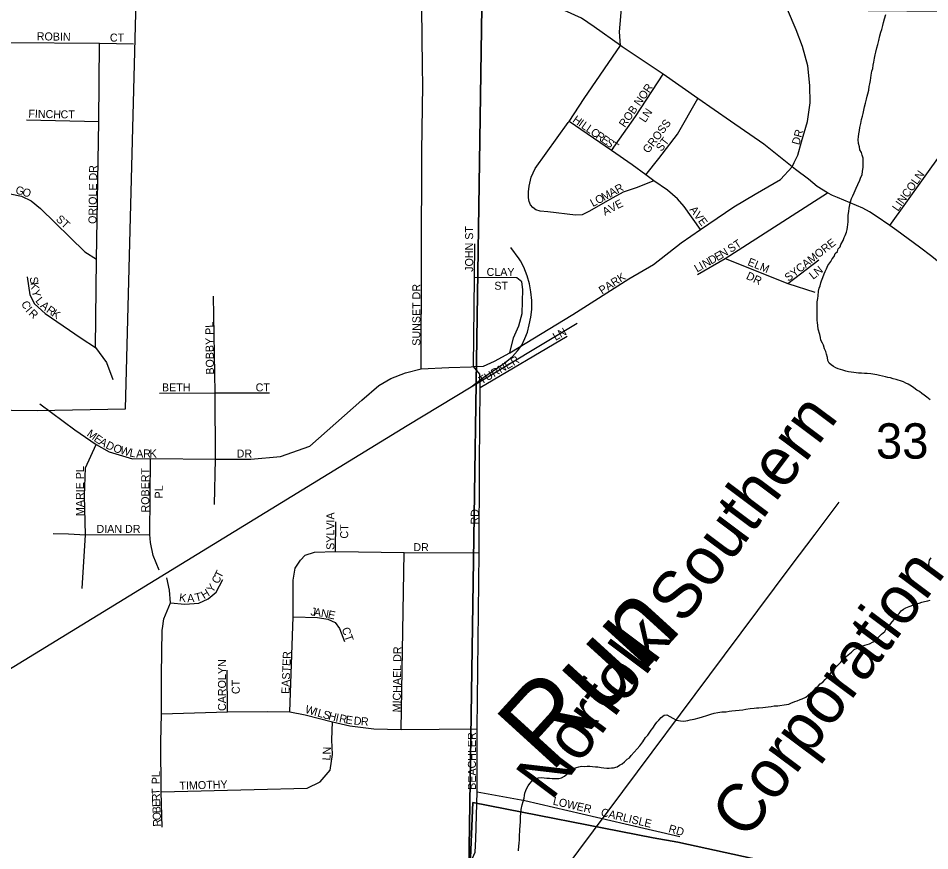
# Model space of a CAD drawing. Extents: x 0 to 1064, y 0 to 440.
# Drawn here: x 135.19 to 152.46, y 390.63 to 406.41 of the extents above; entities that cross this region are included whole.
import ezdxf

# ---------------------------------------------------------------- set-up
doc = ezdxf.new("R2010")
doc.units = 0
for name, color, linetype in [('GM_X_City_Street', 7, 'Continuous'), ('GM_X_City_Street_Text', 7, 'Continuous'), ('GM_X_Corporation', 7, 'Continuous'), ('GM_X_Minor_River', 7, 'Continuous'), ('GM_X_Minor_River_Text', 7, 'Continuous'), ('GM_X_Rail_Line', 7, 'Continuous'), ('GM_X_Rail_Line_Text', 7, 'Continuous'), ('GM_X_Section', 7, 'Continuous'), ('GM_X_Section_Text', 7, 'Continuous'), ('GM_X_State_Route', 7, 'Continuous'), ('GM_X_Township_Subdivision', 7, 'Continuous'), ('GM_X_Township_Subdivision_Text', 7, 'Continuous')]:
    doc.layers.add(name, color=color, linetype=linetype)

msp = doc.modelspace()

# ---------------------------------------------------------------- linework, layer by layer
at = {"layer": 'GM_X_City_Street'}
for points in [[(146.598, 405.89), (146.58, 406.153), (146.624, 406.662), (146.636, 406.826), (146.64, 406.976), (146.673, 407.878), (146.698, 409.622), (146.564, 411.865)], [(142.822, 399.767), (142.839, 403.891), (142.853, 405.135), (142.85, 405.488), (142.839, 406.606)], [(149.888, 403.672), (149.957, 403.815), (150.029, 404.063), (150.14, 404.45), (150.191, 404.805), (150.185, 405.131), (150.148, 405.504), (150.048, 405.87), (149.924, 406.19), (149.763, 406.571)], [(145.611, 404.43), (145.625, 404.448), (145.911, 404.885), (146.598, 405.89)], [(151.702, 402.478), (152.669, 403.837), (152.814, 404.028), (152.905, 404.103), (153.059, 404.203), (153.314, 404.359), (155.028, 405.406), (155.405, 405.642), (155.646, 405.776), (155.732, 405.812), (155.843, 405.827), (156.113, 405.807), (156.319, 405.816)], [(146.429, 403.9), (146.88, 404.548), (147.406, 405.346)], [(147.078, 403.441), (147.325, 403.752), (147.676, 404.21), (148.061, 404.889)], [(147.231, 403.329), (146.897, 403.195), (146.648, 403.114), (146.454, 403.008), (146.001, 402.746), (145.871, 402.68), (145.746, 402.674), (145.223, 402.737), (145.078, 402.752), (144.998, 402.779), (144.937, 402.82), (144.896, 402.872), (144.869, 402.938), (144.854, 403.006), (144.854, 403.121), (144.868, 403.227), (144.907, 403.396), (144.98, 403.562), (145.611, 404.43)], [(148.111, 402.408), (147.807, 402.841), (147.681, 402.984), (147.487, 403.151), (147.231, 403.329), (147.078, 403.441), (146.819, 403.629), (146.429, 403.9), (145.625, 404.448)], [(143.773, 399.806), (143.816, 399.807), (144.005, 399.814), (144.213, 399.91), (144.503, 400.067), (145.695, 400.794), (146.757, 401.473), (147.222, 401.741), (147.746, 402.153), (148.111, 402.408), (148.744, 402.833), (149.147, 403.073), (149.631, 403.35), (149.85, 403.592), (149.888, 403.672)], [(148.055, 401.55), (148.579, 401.854), (150.519, 403.098)], [(143.816, 399.807), (143.837, 401.497), (143.841, 402.133)], [(148.579, 401.854), (149.768, 401.382), (150.276, 401.217)], [(149.768, 401.382), (150.353, 401.83)], [(144.503, 400.067), (144.571, 400.354), (144.672, 400.578), (144.735, 400.812), (144.749, 401.27), (144.732, 401.413), (144.637, 401.49), (143.837, 401.497)], [(138.911, 397.198), (138.932, 398.051), (138.925, 399.309), (138.892, 401.14)], [(143.944, 399.412), (145.591, 400.386)], [(135.605, 399.099), (136.269, 398.61), (136.668, 398.331), (136.919, 398.191), (137.36, 398.058), (137.702, 398.065), (138.932, 398.051), (139.596, 398.051), (140.163, 398.107), (140.713, 398.297), (141.703, 399.17), (142.022, 399.452), (142.252, 399.582), (142.528, 399.69), (142.822, 399.767)], [(142.822, 399.767), (143.351, 399.788), (143.773, 399.806)], [(143.883, 391.754), (143.885, 392.948), (143.925, 396.279), (143.932, 397.971), (143.944, 399.412), (143.938, 399.666), (143.816, 399.807)], [(137.87, 399.302), (138.925, 399.309), (139.953, 399.309)], [(136.408, 395.602), (136.465, 396.618), (136.451, 397.359), (136.469, 397.891), (136.668, 398.331)], [(137.865, 395.95), (137.75, 396.227), (137.696, 396.474), (137.688, 396.625), (137.702, 398.065)], [(141.201, 396.305), (141.207, 396.864)], [(135.857, 396.646), (136.144, 396.639), (136.465, 396.618), (137.688, 396.625)], [(140.339, 393.264), (140.398, 395.068), (140.403, 395.761), (140.439, 395.989), (140.537, 396.141), (140.627, 396.233), (140.806, 396.292), (141.201, 396.305), (142.5, 396.284), (143.925, 396.279)], [(142.444, 392.935), (142.5, 396.284)], [(137.924, 394.847), (137.954, 395.029), (138.079, 395.333), (138.061, 395.575), (138.007, 395.805)], [(138.079, 395.333), (138.347, 395.307), (138.615, 395.325), (138.791, 395.407), (138.941, 395.532), (139.066, 395.774)], [(140.398, 395.068), (140.862, 395.052), (141.056, 395.022), (141.194, 394.958), (141.28, 394.843), (141.372, 394.598)], [(137.918, 391.085), (137.898, 391.751), (137.893, 392.695), (137.908, 393.226), (137.908, 393.966), (137.918, 394.813), (137.924, 394.847)], [(139.16, 393.267), (139.153, 394.057)], [(137.908, 393.226), (139.16, 393.267), (139.908, 393.272), (140.339, 393.264), (140.627, 393.213), (141.148, 393.075), (141.472, 393.004), (141.926, 392.948), (142.444, 392.935), (143.885, 392.948)], [(137.898, 391.751), (139.661, 391.797), (140.666, 391.818), (140.911, 391.94), (141.099, 392.162), (141.143, 392.458), (141.13, 392.736), (141.148, 393.075)], [(132.75, 390.394), (134.757, 390.374), (136.62, 390.376), (136.91, 390.371), (137.013, 390.348), (137.089, 390.3), (137.137, 390.226), (137.163, 389.662), (137.204, 389.562), (137.277, 389.485), (137.431, 389.468), (143.546, 390.366), (143.775, 390.453), (143.847, 390.611), (143.862, 390.856), (143.883, 391.754)], [(143.883, 391.754), (144.786, 391.59), (146.689, 391.147), (147.725, 390.902)]]:
    msp.add_lwpolyline(points, dxfattribs=at)
at = {"layer": 'GM_X_Corporation'}
for points in [[(134.575, 398.988), (135.551, 398.978), (137.228, 399.009), (137.428, 406.746)], [(155.515, 389.139), (151.907, 389.876), (147.686, 390.8), (147.217, 390.877), (143.803, 391.547), (143.754, 390.348), (143.764, 389.078), (140.31, 384.326), (140.059, 384.509), (139.72, 384.042), (139.97, 383.86), (137.379, 383.845), (137.356, 382.071), (137.389, 379.897), (136.812, 379.062), (134.041, 375.398)], [(136.812, 379.062), (137.389, 379.897), (137.356, 382.071), (137.379, 383.845), (139.97, 383.86), (141.136, 383.87), (143.777, 387.503), (143.764, 389.078), (143.754, 390.348), (143.803, 391.547), (147.217, 390.877), (147.686, 390.8), (151.907, 389.876), (155.515, 389.139)]]:
    msp.add_lwpolyline(points, dxfattribs=at)
at = {"layer": 'GM_X_Minor_River'}
for points in [[(151.192, 404.603), (151.205, 404.664), (151.219, 404.731), (151.239, 404.797), (151.258, 404.876), (151.272, 404.93), (151.285, 404.978), (151.299, 405.045), (151.306, 405.112), (151.319, 405.166), (151.333, 405.227), (151.34, 405.281), (151.347, 405.33), (151.361, 405.402), (151.374, 405.457), (151.382, 405.517), (151.395, 405.578), (151.409, 405.651), (151.422, 405.711), (151.436, 405.765), (151.456, 405.844), (151.469, 405.911), (151.489, 405.983), (151.509, 406.074), (151.529, 406.146), (151.548, 406.195), (151.568, 406.273), (151.581, 406.328), (151.601, 406.394), (151.621, 406.479)], [(151.66, 399.601), (151.618, 399.614), (151.563, 399.628), (151.503, 399.641), (151.455, 399.654), (151.412, 399.655), (151.34, 399.669), (151.267, 399.677), (151.218, 399.678), (151.164, 399.685), (151.103, 399.686), (151.019, 399.694), (150.916, 399.709), (150.867, 399.722), (150.807, 399.741), (150.765, 399.754), (150.723, 399.768), (150.675, 399.787), (150.633, 399.812), (150.591, 399.843), (150.549, 399.875), (150.526, 399.924), (150.521, 399.979), (150.498, 400.04), (150.487, 400.095), (150.464, 400.144), (150.441, 400.211), (150.424, 400.254), (150.395, 400.31), (150.384, 400.359), (150.373, 400.414), (150.345, 400.518), (150.334, 400.585), (150.329, 400.64), (150.324, 400.682), (150.325, 400.737), (150.326, 400.786), (150.321, 400.834), (150.322, 400.877), (150.323, 400.919), (150.324, 400.968), (150.325, 401.035), (150.333, 401.096), (150.34, 401.15), (150.348, 401.235), (150.361, 401.296), (150.381, 401.338), (150.394, 401.392), (150.407, 401.434), (150.432, 401.495), (150.458, 401.567), (150.477, 401.609), (150.497, 401.657), (150.528, 401.724), (150.579, 401.796), (150.604, 401.85), (150.647, 401.891), (150.667, 401.952), (150.71, 401.987), (150.723, 402.036), (150.761, 402.077), (150.774, 402.12), (150.818, 402.198), (150.837, 402.252), (150.856, 402.294), (150.876, 402.355), (150.889, 402.403), (150.896, 402.451), (150.911, 402.548), (150.912, 402.615), (150.913, 402.676), (150.921, 402.743), (150.928, 402.809), (150.942, 402.87), (150.955, 402.93), (150.975, 402.991), (151, 403.045), (151.026, 403.099), (151.064, 403.19), (151.096, 403.256), (151.128, 403.34), (151.147, 403.394), (151.173, 403.443), (151.18, 403.509), (151.194, 403.582), (151.196, 403.685), (151.192, 403.758), (151.175, 403.813), (151.164, 403.862), (151.134, 403.912), (151.124, 403.973), (151.107, 404.034), (151.102, 404.107), (151.103, 404.162), (151.111, 404.216), (151.124, 404.283), (151.131, 404.337), (151.151, 404.416), (151.165, 404.489), (151.179, 404.549), (151.192, 404.603)], [(152.464, 399.176), (152.398, 399.226), (152.35, 399.264), (152.303, 399.301), (152.261, 399.333), (152.213, 399.364), (152.153, 399.408), (152.111, 399.439), (152.045, 399.477), (152.003, 399.496), (151.955, 399.522), (151.901, 399.535), (151.859, 399.548), (151.817, 399.561), (151.762, 399.575), (151.714, 399.594), (151.66, 399.601)], [(152.467, 395.965), (152.45, 396.014), (152.439, 396.057), (152.446, 396.1), (152.453, 396.142), (152.484, 396.184)], [(151.959, 395.21), (152.002, 395.24), (152.063, 395.262), (152.106, 395.274), (152.18, 395.309), (152.253, 395.325), (152.302, 395.342), (152.357, 395.36), (152.418, 395.37), (152.46, 395.382)], [(146.426, 392.204), (146.468, 392.204), (146.535, 392.226), (146.579, 392.256), (146.628, 392.279), (146.677, 392.321), (146.727, 392.368), (146.77, 392.398), (146.801, 392.44), (146.857, 392.505), (146.913, 392.565), (146.963, 392.625), (147.019, 392.696), (147.075, 392.78), (147.119, 392.828), (147.182, 392.918), (147.213, 392.96), (147.257, 393.026), (147.288, 393.068), (147.325, 393.109), (147.369, 393.157), (147.424, 393.205), (147.479, 393.209), (147.533, 393.178), (147.587, 393.146), (147.659, 393.108), (147.732, 393.094), (147.786, 393.093), (147.835, 393.098), (147.877, 393.103), (147.92, 393.115), (147.993, 393.125), (148.091, 393.153), (148.152, 393.17), (148.231, 393.199), (148.311, 393.222), (148.372, 393.239), (148.439, 393.255), (148.518, 393.266), (148.597, 393.27), (148.658, 393.281), (148.707, 393.286), (148.774, 393.291), (148.847, 393.301), (148.914, 393.306), (148.974, 393.317), (149.054, 393.327), (149.133, 393.338), (149.175, 393.343), (149.218, 393.342), (149.291, 393.352), (149.394, 393.362), (149.449, 393.367), (149.51, 393.378), (149.577, 393.383), (149.619, 393.388), (149.698, 393.398), (149.784, 393.415), (149.827, 393.432), (149.9, 393.461), (149.943, 393.478), (149.998, 393.501), (150.041, 393.512), (150.108, 393.547), (150.152, 393.583), (150.201, 393.624), (150.257, 393.672), (150.3, 393.72), (150.343, 393.755), (150.381, 393.797), (150.43, 393.832), (150.474, 393.88), (150.529, 393.94), (150.561, 393.982), (150.604, 394.029), (150.66, 394.095), (150.722, 394.16), (150.772, 394.208), (150.816, 394.262), (150.865, 394.309), (150.908, 394.345), (150.976, 394.398), (151.026, 394.446), (151.081, 394.475), (151.124, 394.492), (151.173, 394.516), (151.228, 394.527), (151.314, 394.555), (151.381, 394.596), (151.436, 394.625), (151.474, 394.667), (151.542, 394.739), (151.604, 394.786), (151.636, 394.852), (151.698, 394.918), (151.741, 394.972), (151.785, 395.025), (151.817, 395.079), (151.878, 395.133), (151.916, 395.181), (151.959, 395.21)], [(144.668, 390.631), (144.676, 390.728), (144.677, 390.771), (144.685, 390.849), (144.686, 390.904), (144.695, 391.032), (144.697, 391.111), (144.704, 391.184), (144.706, 391.281), (144.714, 391.342), (144.721, 391.414), (144.736, 391.505), (144.755, 391.566), (144.775, 391.632), (144.782, 391.681), (144.789, 391.729), (144.808, 391.777), (144.827, 391.82), (144.852, 391.862), (144.884, 391.91), (144.927, 391.957), (144.989, 391.999), (145.044, 392.016), (145.099, 392.02), (145.153, 392.019), (145.202, 392.012), (145.256, 392.011), (145.305, 392.004), (145.365, 392.003), (145.432, 392.001), (145.481, 392.018), (145.536, 392.047), (145.586, 392.095), (145.617, 392.137), (145.666, 392.172), (145.709, 392.196), (145.764, 392.213), (145.807, 392.224), (145.862, 392.235), (145.917, 392.234), (145.965, 392.239), (146.02, 392.238), (146.068, 392.23), (146.123, 392.223), (146.171, 392.222), (146.232, 392.215), (146.286, 392.207), (146.341, 392.2), (146.383, 392.199), (146.426, 392.204)]]:
    msp.add_lwpolyline(points, dxfattribs=at)
at = {"layer": 'GM_X_Rail_Line'}
for points in [[(144.68, 401.85), (144.524, 402.067)], [(143.768, 399.423), (144.01, 399.608), (144.411, 399.876), (144.551, 399.996), (144.648, 400.105), (144.73, 400.213), (144.79, 400.342), (144.835, 400.459), (144.872, 400.601), (144.903, 400.745), (144.919, 400.887), (144.921, 401.062), (144.903, 401.222), (144.874, 401.373), (144.832, 401.528), (144.766, 401.69), (144.704, 401.812), (144.68, 401.85)], [(143.768, 399.423), (145.776, 400.633)], [(111.177, 379.476), (120.304, 385.063), (131.83, 392.117), (142.562, 398.69), (143.768, 399.423)], [(149.833, 396.034), (150.284, 396.636), (150.74, 397.239)], [(148.567, 394.342), (149.833, 396.034)], [(125.514, 363.557), (131.089, 371.031), (137.36, 379.324), (139.774, 382.56), (144.164, 388.431), (148.567, 394.342)]]:
    msp.add_lwpolyline(points, dxfattribs=at)
at = {"layer": 'GM_X_Section'}
for points in [[(127.601, 406.619), (143.975, 406.617), (143.725, 390.273), (127.547, 390.367)], [(143.975, 406.617), (160.061, 406.476), (160.036, 390.151), (143.725, 390.273)]]:
    msp.add_lwpolyline(points, close=True, dxfattribs=at)
at = {"layer": 'GM_X_State_Route'}
for points in [[(146.632, 405.867), (146.598, 405.89), (146.103, 406.243), (145.859, 406.41), (145.536, 406.557), (142.839, 406.606), (142.812, 406.606)], [(149.915, 403.543), (149.85, 403.592), (149.314, 404.022), (148.684, 404.455), (148.061, 404.889), (147.406, 405.346), (146.632, 405.867)], [(151.83, 402.384), (151.702, 402.478), (151.443, 402.659), (151.316, 402.738), (151.189, 402.807), (150.71, 403.014), (150.612, 403.051), (150.519, 403.098), (150.323, 403.221), (150.161, 403.359), (149.915, 403.543)], [(152.97, 401.517), (152.803, 401.644), (152.496, 401.895), (152.261, 402.068), (151.83, 402.384)]]:
    msp.add_lwpolyline(points, dxfattribs=at)
at = {"layer": 'GM_X_Township_Subdivision'}
for points in [[(134.127, 405.965), (135.025, 405.949), (136.736, 405.933), (137.376, 405.921)], [(136.657, 400.172), (136.678, 401.846), (136.72, 404.453), (136.736, 405.933)], [(135.35, 404.481), (136.72, 404.453)], [(134.089, 403.087), (134.396, 403.083), (135.043, 403.08), (135.256, 403.034), (135.438, 402.951), (135.619, 402.804), (136.458, 401.983), (136.678, 401.846)], [(135.364, 401.507), (135.417, 401.168), (135.504, 400.994), (135.703, 400.815), (136.385, 400.347), (136.657, 400.172), (136.867, 399.886), (136.986, 399.564)]]:
    msp.add_lwpolyline(points, dxfattribs=at)

# ---------------------------------------------------------------- texts
at = {"layer": 'GM_X_City_Street_Text'}
for s, height, rotation, p in [('ROB NOR', 0.1515, 55.005, (146.68, 404.327)), ('LN', 0.1515, 55.4949, (147.065, 404.419)), ('H', 0.152, 324.9883, (145.679, 404.453)), ('I', 0.152, 325.014, (145.789, 404.376)), ('L', 0.152, 325.0214, (145.843, 404.338)), ('GROSS', 0.1515, 53.132, (147.126, 403.836)), ('L', 0.152, 324.9767, (145.931, 404.277)), ('C', 0.152, 324.9928, (146.018, 404.216)), ('R', 0.152, 325.0093, (146.116, 404.147)), ('DR', 0.1515, 74.4709, (149.984, 403.996)), ('E', 0.152, 325.0266, (146.215, 404.078)), ('S', 0.152, 324.961, (146.302, 404.017)), ('ST', 0.1515, 52.4265, (147.375, 403.872)), ('T', 0.152, 326.7001, (146.394, 403.953)), ('LINCOLN', 0.1515, 54.4644, (151.853, 402.739)), ('R', 0.152, 28.3896, (146.544, 403.084)), ('O', 0.152, 28.6977, (146.17, 402.879)), ('M', 0.152, 28.7021, (146.287, 402.943)), ('A', 0.152, 28.6977, (146.427, 403.02)), ('L', 0.152, 28.6671, (146.076, 402.828)), ('AVE', 0.1515, 27.4123, (146.304, 402.664)), ('AVE', 0.1515, 306.4786, (147.899, 402.78)), ('JOHN ST', 0.1515, 90, (143.808, 401.603)), ('ST', 0.1515, 32.7431, (148.688, 401.96)), ('SYCAMORE', 0.1515, 38.0704, (149.779, 401.412)), ('N', 0.152, 31.8566, (148.53, 401.86)), ('N', 0.152, 29.528, (148.2, 401.673)), ('D', 0.152, 29.528, (148.316, 401.739)), ('E', 0.152, 29.5348, (148.432, 401.804)), ('ELM', 0.1515, 337.8311, (148.993, 401.734)), ('CLAY', 0.1515, 0, (144.063, 401.525)), ('L', 0.152, 29.5348, (148.049, 401.588)), ('I', 0.152, 29.5388, (148.142, 401.64)), ('LN', 0.1515, 38.6563, (150.246, 401.45)), ('PARK', 0.1515, 32.8256, (146.249, 401.172)), ('DR', 0.1515, 334.7927, (148.965, 401.475)), ('SUNSET DR', 0.1515, 90, (142.808, 400.203)), ('ST', 0.1515, 0, (144.21, 401.264)), ('BOBBY PL', 0.1515, 90.8421, (138.901, 399.656)), ('LN', 0.1515, 29.361, (145.369, 400.294)), ('TURNER', 0.1515, 30.2562, (143.969, 399.467)), ('BETH', 0.1515, 0, (137.916, 399.338)), ('CT', 0.1515, 0, (139.69, 399.338)), ('M', 0.152, 323.8842, (136.48, 398.506)), ('E', 0.152, 325.8614, (136.614, 398.408)), ('A', 0.152, 329.5473, (136.711, 398.342)), ('D', 0.152, 333.8931, (136.837, 398.269)), ('O', 0.152, 342.7614, (136.981, 398.201)), ('W', 0.152, 343.3627, (137.11, 398.161)), ('L', 0.152, 349.669, (137.294, 398.107)), ('A', 0.152, 359.7337, (137.427, 398.085)), ('R', 0.152, 359.9941, (137.561, 398.085)), ('K', 0.152, 359.9929, (137.681, 398.085)), ('DR', 0.1515, 0, (139.33, 398.085)), ('MARIE PL', 0.1515, 90, (136.437, 396.976)), ('ROBERT', 0.1515, 90, (137.675, 397.043)), ('PL', 0.1515, 90, (137.932, 397.309)), ('SYLVIA', 0.1515, 90, (141.181, 396.336)), ('RD', 0.1515, 90, (143.915, 396.816)), ('DIAN DR', 0.1515, 0, (136.676, 396.657)), ('CT', 0.1515, 90, (141.442, 396.549)), ('DR', 0.1515, 0, (142.676, 396.311)), ('C', 0.152, 63.3351, (138.983, 395.68)), ('T', 0.152, 63.419, (139.037, 395.787)), ('Y', 0.152, 53.9113, (138.872, 395.513)), ('K', 0.152, 351.6659, (138.232, 395.363)), ('A', 0.152, 3.1403, (138.397, 395.342)), ('T', 0.152, 13.6306, (138.56, 395.354)), ('H', 0.152, 31.9658, (138.712, 395.4)), ('J', 0.152, 350.8683, (140.721, 395.098)), ('A', 0.152, 350.888, (140.787, 395.087)), ('N', 0.152, 350.4694, (140.918, 395.066)), ('E', 0.152, 348.1113, (141.048, 395.044)), ('CT', 0.1515, 289.4353, (141.317, 394.839)), ('MICHAEL DR', 0.1515, 89.3341, (142.435, 393.256)), ('CAROLYN', 0.1515, 90, (139.128, 393.283)), ('EASTER', 0.1515, 87.7987, (140.328, 393.604)), ('CT', 0.1515, 90, (139.389, 393.603)), ('W', 0.152, 342.8305, (140.615, 393.252)), ('I', 0.152, 344.2906, (140.785, 393.2)), ('L', 0.152, 344.2873, (140.849, 393.182)), ('S', 0.152, 344.2873, (140.952, 393.153)), ('H', 0.152, 345.6748, (141.058, 393.123)), ('I', 0.152, 348.3325, (141.195, 393.089)), ('R', 0.152, 348.8181, (141.262, 393.075)), ('E', 0.152, 350.4157, (141.384, 393.051)), ('D', 0.152, 355.4431, (141.543, 393.027)), ('R', 0.152, 355.5928, (141.677, 393.016)), ('BEACHLER', 0.1515, 90, (143.861, 391.789)), ('N', 0.152, 88.7393, (141.112, 392.457)), ('L', 0.152, 84.855, (141.102, 392.34)), ('PL', 0.1515, 90, (137.875, 391.896)), ('TIMOTHY', 0.1515, 1.7888, (138.249, 391.791)), ('T', 0.152, 91.3392, (137.877, 391.694)), ('R', 0.152, 92.2854, (137.882, 391.575)), ('LOWER', 0.1515, 347.0899, (145.309, 391.511)), ('E', 0.152, 92.2677, (137.886, 391.468)), ('B', 0.152, 92.2975, (137.891, 391.348)), ('O', 0.152, 92.2732, (137.897, 391.215)), ('CARLISLE', 0.1515, 346.5067, (146.217, 391.297)), ('R', 0.152, 92.2829, (137.901, 391.095)), ('RD', 0.1515, 344.4627, (147.497, 390.99))]:
    msp.add_text(s, height=height, rotation=rotation, dxfattribs=at).set_placement(p)
at = {"layer": 'GM_X_Minor_River_Text'}
msp.add_text('Run', height=1.5154, rotation=47.6356, dxfattribs=at).set_placement((145.279, 392.088))
at = {"layer": 'GM_X_Rail_Line_Text'}
for s, rotation, p in [('Norfolk Southern', 53.1591, (145.29, 391.56)), ('Corporation', 53.2781, (148.985, 390.819))]:
    msp.add_text(s, height=0.90606, rotation=rotation, dxfattribs=at).set_placement(p)
at = {"layer": 'GM_X_Section_Text'}
msp.add_text('33', height=0.6697, rotation=0, dxfattribs=at).set_placement((151.436, 398.064))
at = {"layer": 'GM_X_Township_Subdivision_Text'}
for s, height, rotation, p in [('ROBIN', 0.1515, 358.9197, (135.544, 405.991)), ('CT', 0.1515, 0, (136.93, 405.965)), ('FINCH', 0.1515, 358.6368, (135.384, 404.525)), ('CT', 0.1515, 0, (135.996, 404.511)), ('ORIOLE DR', 0.1515, 89.2262, (136.675, 402.51)), ('G', 0.152, 345.5502, (135.132, 403.088)), ('O', 0.152, 342.2287, (135.259, 403.055)), ('ST', 0.1515, 317.4986, (135.896, 402.584)), ('S', 0.152, 277.6199, (135.411, 401.499)), ('K', 0.152, 277.6322, (135.426, 401.393)), ('Y', 0.152, 284.2332, (135.447, 401.242)), ('C', 0.152, 294.3495, (135.247, 401.012)), ('L', 0.152, 308.8471, (135.511, 401.05)), ('A', 0.152, 319.7566, (135.6, 400.944)), ('I', 0.152, 311.0281, (135.322, 400.862)), ('R', 0.152, 317.4901, (135.379, 400.798)), ('R', 0.152, 324.6724, (135.713, 400.849)), ('K', 0.152, 326.8591, (135.816, 400.776))]:
    msp.add_text(s, height=height, rotation=rotation, dxfattribs=at).set_placement(p)

doc.saveas('drawing.dxf')
